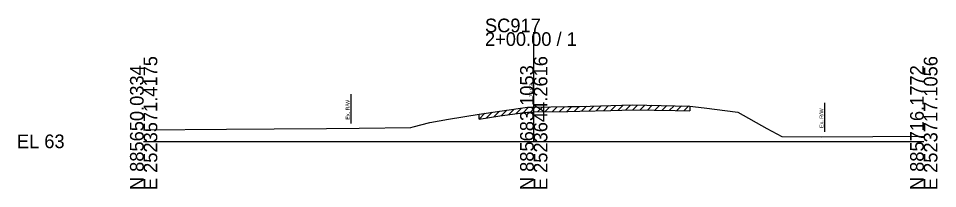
# Model space of a CAD drawing. Extents: x -26 to 218, y -10 to 12021.
# Drawn here: x -25.7 to 162.8, y 1990.3 to 2025.2 of the extents above; entities that cross this region are included whole.
import ezdxf

# ---------------------------------------------------------------- set-up
doc = ezdxf.new("R2010")
doc.units = 0
for name, color, linetype in [('RD_GPK_XS_Cell', 7, 'Continuous'), ('RD_XS_ExGround', 7, 'Continuous'), ('RD_XS_ExPaveRet', 7, 'Continuous'), ('RD_XS_ExRW', 7, 'Continuous'), ('RD_XS_TX_Elev_EX', 7, 'Continuous')]:
    doc.layers.add(name, color=color, linetype=linetype)

msp = doc.modelspace()

# ---------------------------------------------------------------- linework, layer by layer
at = {"layer": 'RD_GPK_XS_Cell'}
for p, q in [((80, 2000), (80, 2022.37)), ((0, 2000), (80, 2000)), ((80, 2000), (160, 2000))]:
    msp.add_line(p, q, dxfattribs=at)
at = {"layer": 'RD_XS_ExGround'}
for p, q in [((68.81, 2005.58), (73.06, 2006.2)), ((73.06, 2006.2), (78.7, 2007)), ((78.7, 2007), (80, 2007.02)), ((80, 2007.02), (87, 2007.12)), ((87, 2007.12), (89.49, 2007.16)), ((89.49, 2007.16), (95.8, 2007.33)), ((95.8, 2007.33), (100.36, 2007.46)), ((100.36, 2007.46), (108.98, 2007.3)), ((108.98, 2007.3), (112, 2007.24)), ((112, 2007.24), (114.98, 2006.87)), ((114.98, 2006.87), (121.87, 2005.98)), ((58.69, 2003.89), (62.51, 2004.54)), ((62.51, 2004.54), (68.81, 2005.58)), ((121.87, 2005.98), (127.78, 2002.61)), ((0, 2002.37), (16.99, 2002.49)), ((16.99, 2002.49), (26.74, 2002.56)), ((26.74, 2002.56), (37.51, 2002.61)), ((37.51, 2002.61), (44.17, 2002.67)), ((44.17, 2002.67), (54.78, 2002.84)), ((54.78, 2002.84), (55.26, 2002.97)), ((55.26, 2002.97), (58.69, 2003.89)), ((127.78, 2002.61), (130.92, 2000.98)), ((130.92, 2000.98), (139.07, 2000.93)), ((139.07, 2000.93), (160, 2001.03))]:
    msp.add_line(p, q, dxfattribs=at)
at = {"layer": 'RD_XS_ExPaveRet'}
for p, q in [((71.81, 2005.02), (72.98, 2006.19)), ((73.06, 2005.2), (78.7, 2006)), ((73.31, 2005.23), (74.47, 2006.4)), ((74.81, 2005.45), (75.97, 2006.61)), ((76.31, 2005.66), (77.47, 2006.83)), ((77.81, 2005.87), (78.94, 2007)), ((78.7, 2006), (80, 2006.02)), ((79.31, 2006.01), (80.32, 2007.02)), ((80, 2006.02), (87, 2006.12)), ((80.81, 2006.03), (81.82, 2007.04)), ((82.31, 2006.05), (83.32, 2007.07)), ((83.81, 2006.07), (84.82, 2007.09)), ((85.31, 2006.09), (86.32, 2007.11)), ((86.81, 2006.12), (87.82, 2007.13)), ((87, 2006.12), (89.49, 2006.16)), ((88.31, 2006.14), (89.32, 2007.15)), ((89.49, 2006.16), (95.8, 2006.33)), ((89.81, 2006.17), (90.84, 2007.19)), ((91.31, 2006.21), (92.34, 2007.23)), ((92.81, 2006.25), (93.84, 2007.27)), ((94.31, 2006.29), (95.34, 2007.32)), ((95.8, 2006.33), (100.36, 2006.46)), ((95.81, 2006.33), (96.84, 2007.36)), ((97.31, 2006.37), (98.34, 2007.4)), ((98.81, 2006.41), (99.84, 2007.44)), ((100.31, 2006.46), (101.29, 2007.44)), ((100.36, 2006.46), (108.98, 2006.3)), ((101.81, 2006.43), (102.79, 2007.41)), ((103.31, 2006.4), (104.29, 2007.39)), ((104.81, 2006.38), (105.79, 2007.36)), ((106.31, 2006.35), (107.29, 2007.33)), ((107.81, 2006.32), (108.79, 2007.3)), ((108.98, 2006.3), (112, 2006.24)), ((109.31, 2006.29), (110.29, 2007.28)), ((110.81, 2006.27), (111.79, 2007.25)), ((112, 2007.24), (112, 2006.24)), ((68.81, 2004.58), (69.98, 2005.75)), ((68.81, 2004.58), (68.81, 2005.58)), ((68.81, 2004.58), (73.06, 2005.2)), ((70.31, 2004.8), (71.48, 2005.97))]:
    msp.add_line(p, q, dxfattribs=at)
at = {"layer": 'RD_XS_ExRW'}
for p, q in [((42.5, 2009.65), (42.5, 2003.65)), ((139.67, 2007.93), (139.67, 2001.93))]:
    msp.add_line(p, q, dxfattribs=at)

# ---------------------------------------------------------------- texts
at = {"layer": 'RD_GPK_XS_Cell'}
for s, p in [('SC917', (70, 2022.37)), ('2+00.00 / 1', (70, 2019.57)), ('EL 63', (-26, 1998.6))]:
    msp.add_text(s, height=2.8, dxfattribs=at).set_placement(p)
for s, p in [('E 2523571.4175', (2.8, 1990)), ('E 2523644.2616', (82.8, 1990)), ('E 2523717.1056', (162.8, 1990)), ('N 885650.0334', (0, 1990)), ('N 885683.1053', (80, 1990)), ('N 885716.1772', (160, 1990))]:
    msp.add_text(s, height=2.8, rotation=90, dxfattribs=at).set_placement(p)
at = {"layer": 'RD_XS_ExRW'}
for p in [(42.25, 2004.44), (139.42, 2002.72)]:
    msp.add_text('Ex. R/W ', height=0.8, rotation=90, dxfattribs=at).set_placement(p)
at = {"layer": 'RD_XS_TX_Elev_EX'}
msp.add_text('70.02', height=0.8, rotation=90, dxfattribs=at).set_placement((79.9, 2009.02))

doc.saveas('drawing.dxf')
